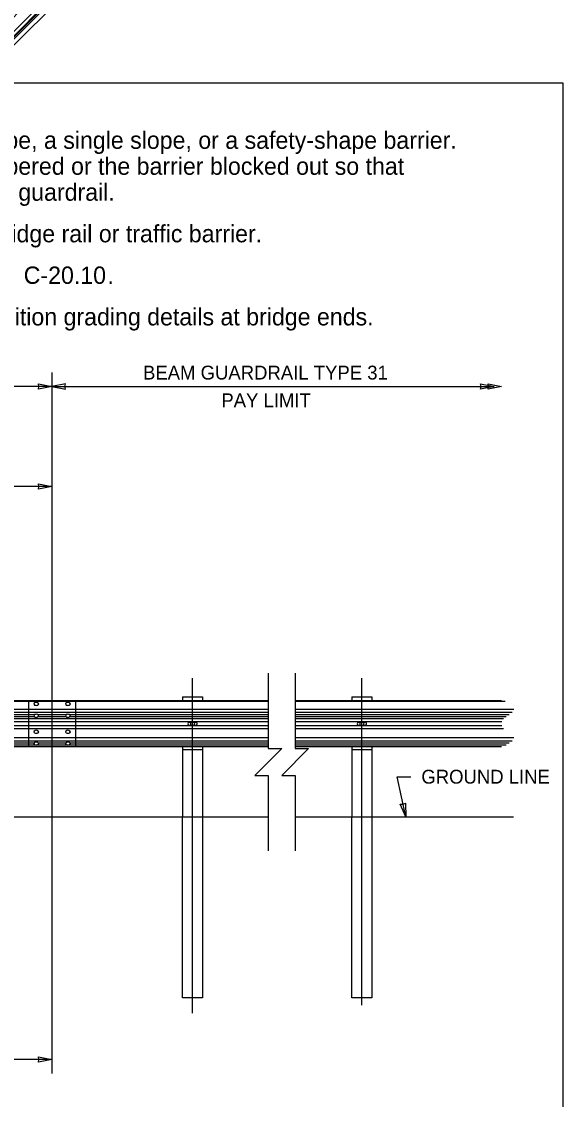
# Model space of a CAD drawing. Extents: x 34446 to 262144, y 33903 to 262144.
# Drawn here: x 102525 to 103145, y 100902 to 102147 of the extents above; entities that cross this region are included whole.
import ezdxf

# ---------------------------------------------------------------- set-up
doc = ezdxf.new("R2010")
doc.units = 0
for name, color, linetype in [('Level 1', 7, 'Continuous'), ('Level 11', 7, 'Continuous'), ('Level 12', 7, 'Continuous'), ('Level 15', 7, 'Continuous'), ('Level 2', 7, 'Continuous'), ('Level 20', 7, 'Continuous'), ('Level 5', 7, 'Continuous'), ('Level 8', 7, 'Continuous'), ('Level 9', 7, 'Continuous')]:
    doc.layers.add(name, color=color, linetype=linetype)

msp = doc.modelspace()

# ---------------------------------------------------------------- linework, layer by layer
at = {"layer": 'Level 1'}
for p, q in [((102710.8896889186, 101019.11407565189), (102710.8896889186, 101227.93343138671)), ((102733.9195840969, 101228.01685343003), (102733.9195840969, 101019.11407565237)), ((102906.69542888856, 101019.03065360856), (102906.69542888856, 101227.85000934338)), ((102929.72532406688, 101227.93343138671), (102929.72532406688, 101019.03065360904)), ((102733.9195840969, 101019.11407565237), (102710.8896889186, 101019.11407565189)), ((102929.72532406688, 101019.03065360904), (102906.69542888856, 101019.03065360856))]:
    msp.add_line(p, q, dxfattribs=at)
msp.add_lwpolyline([(99862, 99999.5), (103151, 99999.5), (103151, 102075.5), (99862, 102075.5)], close=True, dxfattribs=at)
at = {"layer": 'Level 11'}
for p, q in [((99885.83988098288, 101227.93343138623), (102809.9793919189, 101227.93343138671)), ((102840.9511302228, 101227.93343138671), (103093.23909765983, 101227.93343138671))]:
    msp.add_line(p, q, dxfattribs=at)
at = {"layer": 'Level 12'}
for p, q in [((102809.97939189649, 101362.26849800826), (101882.86191114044, 101362.26849800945)), ((102532.8619111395, 101362.26849805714), (102532.8619111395, 101308.91433139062)), ((102587.02857780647, 101362.26849805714), (102587.02857780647, 101308.91433139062)), ((103079.7091010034, 101362.26849800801), (102840.95113020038, 101362.26849800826)), ((102809.97939191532, 101308.91433138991), (101882.86191114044, 101308.91433138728)), ((103079.7091010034, 101308.91433139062), (102840.95113021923, 101308.91433138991))]:
    msp.add_line(p, q, dxfattribs=at)
for points in [[(102721.0121291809, 101337.21644837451), (102718.65357780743, 101337.21644837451)], [(102726.23691114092, 101337.21644837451), (102723.87835976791, 101337.21644837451)], [(102916.73665321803, 101337.21644837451), (102914.37810184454, 101337.21644837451)], [(102921.96143517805, 101337.21644837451), (102919.60288380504, 101337.21644837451)], [(102718.65357780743, 101333.96644837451), (102721.0121291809, 101333.96644837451)], [(102723.87835976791, 101333.96644837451), (102726.23691114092, 101333.96644837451)], [(102914.37810184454, 101333.96644837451), (102916.73665321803, 101333.96644837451)], [(102919.60288380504, 101333.96644837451), (102921.96143517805, 101333.96644837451)]]:
    msp.add_lwpolyline(points, dxfattribs=at)
for centre in [(102722.44524447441, 101335.59144837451), (102918.16976851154, 101335.59144837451)]:
    msp.add_circle(centre, 2.1666666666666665, dxfattribs=at)
for centre, start, end in [((102718.65357780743, 101335.59144837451), 90, 270), ((102726.23691114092, 101335.59144837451), 269.9999999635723, 90), ((102914.37810184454, 101335.59144837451), 90, 270), ((102921.96143517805, 101335.59144837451), 269.9999999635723, 90)]:
    msp.add_arc(centre, 1.625, start, end, dxfattribs=at)
at = {"layer": 'Level 15'}
for p, q in [((102559.94524447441, 101741.28379139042), (102559.94524447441, 100931.71120916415)), ((102559.94524447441, 101725.28379139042), (99958.9827143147, 101725.28379139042)), ((102559.94524447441, 101725.28379139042), (103070.90514361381, 101725.28379139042)), ((102559.94524447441, 101609.7282358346), (102397.44524447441, 101609.7282358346)), ((102722.44524447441, 101001.35266726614), (102722.44524447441, 101388.2667647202)), ((102918.10946834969, 101010.59243242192), (102918.10946834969, 101388.2667647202)), ((102968.84541737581, 101227.93343138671), (102958.97828765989, 101274.43452072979)), ((102958.97828765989, 101274.43452072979), (102974.90328290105, 101274.43452072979)), ((102559.94524447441, 100947.71120916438), (101909.94524447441, 100947.71120916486))]:
    msp.add_line(p, q, dxfattribs=at)
for points in [[(102559.94524447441, 101725.28379139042), (102544.21709884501, 101722.1991744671), (102544.94524447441, 101725.28379139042), (102544.21709884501, 101728.36840831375)], [(102559.94524447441, 101725.28379139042), (102575.67339010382, 101722.1991744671), (102574.94524447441, 101725.28379139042), (102575.67339010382, 101728.36840831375)], [(103070.90514361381, 101725.28379139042), (103055.17699798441, 101722.1991744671), (103055.90514361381, 101725.28379139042), (103055.17699798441, 101728.36840831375)], [(103079.7091010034, 101725.28379139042), (103063.980955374, 101722.1991744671), (103064.7091010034, 101725.28379139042), (103063.980955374, 101728.36840831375)], [(102559.94524447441, 101609.7282358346), (102544.21709884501, 101606.64361891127), (102544.94524447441, 101609.7282358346), (102544.21709884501, 101612.81285275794)], [(102968.84541737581, 101227.93343138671), (102962.56329351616, 101242.67874746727), (102965.73186917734, 101242.60673427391), (102968.59816263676, 101243.95929459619)], [(102559.94524447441, 100947.71120916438), (102544.21709884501, 100944.62659224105), (102544.94524447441, 100947.71120916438), (102544.21709884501, 100950.79582608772)]]:
    msp.add_lwpolyline(points, close=True, dxfattribs=at)
for points in [[(102809.97939188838, 101394.07740407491), (102809.9793919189, 101306.96911570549), (102825.4652610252, 101306.96911570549), (102794.49352278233, 101275.99737743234), (102809.9793919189, 101275.99737743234), (102809.9793919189, 101188.88936348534)], [(102840.95113019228, 101394.07740407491), (102840.9511302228, 101306.96911570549), (102856.43699932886, 101306.96911570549), (102825.46526105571, 101275.99737743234), (102840.9511302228, 101275.99737743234), (102840.9511302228, 101188.88936348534)]]:
    msp.add_lwpolyline(points, dxfattribs=at)
at = {"layer": 'Level 2'}
for p, q in [((102710.8896889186, 101366.60009805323), (102734.00080002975, 101366.60009805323)), ((102710.8896889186, 101366.60009805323), (102710.8896889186, 101362.26849805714)), ((102734.00080002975, 101366.60009805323), (102734.00080002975, 101362.26849805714)), ((102906.61421295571, 101366.60009805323), (102929.72532406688, 101366.60009805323)), ((102906.61421295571, 101366.60009805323), (102906.61421295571, 101362.26849805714)), ((102929.72532406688, 101366.60009805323), (102929.72532406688, 101362.26849805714)), ((102710.8896889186, 101308.91433139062), (102710.8896889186, 101305.93343138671)), ((102710.8896889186, 101305.93343138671), (102734.00080002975, 101305.93343138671)), ((102710.8896889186, 101305.93343138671), (102710.8896889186, 101227.93343138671)), ((102734.00080002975, 101308.91433139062), (102734.00080002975, 101305.93343138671)), ((102734.00080002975, 101305.93343138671), (102734.00080002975, 101227.93343138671)), ((102906.61421295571, 101308.91433139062), (102906.61421295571, 101305.93343138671)), ((102906.61421295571, 101305.93343138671), (102929.72532406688, 101305.93343138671)), ((102906.61421295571, 101305.93343138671), (102906.61421295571, 101227.93343138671)), ((102929.72532406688, 101308.91433139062), (102929.72532406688, 101305.93343138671)), ((102929.72532406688, 101305.93343138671), (102929.72532406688, 101227.93343138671))]:
    msp.add_line(p, q, dxfattribs=at)
at = {"layer": 'Level 5'}
msp.add_spline([(100965.33493063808, 100576.21973024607), (100979.73117748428, 100581.07419127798), (100976.64599230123, 100587.06308016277), (100980.63858489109, 100590.14826534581), (100978.82377007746, 100594.86678386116), (100978.82377007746, 100594.86678386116), (100972.34760629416, 100605.2602740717)], degree=3, dxfattribs=at)
at = {"layer": 'Level 8'}
for centre, start, end in [((102541.76641671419, 101356.56389125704), 50.43711929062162, 129.5628807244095), ((102578.39250793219, 101356.56389125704), 50.43711929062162, 129.56288072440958), ((102541.76627779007, 101346.78748786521), 230.4371192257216, 309.5628807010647), ((102578.39236900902, 101346.78748786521), 230.4371192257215, 309.56288070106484), ((102541.76627779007, 101324.39336530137), 50.43711929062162, 129.5628807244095), ((102578.39236900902, 101324.39336530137), 50.43711929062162, 129.56288072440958), ((102541.76627779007, 101314.6169619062), 230.4371192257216, 309.5628807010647), ((102578.39236900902, 101314.6169619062), 230.4371192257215, 309.56288070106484)]:
    msp.add_arc(centre, 3.6438845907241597, start, end, dxfattribs=at)
for centre, major_axis, ratio, start_param, end_param in [((102541.76641671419, 101358.44176386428), (2.828893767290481, 9.525007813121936e-11), 0.5757772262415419, 2.5329409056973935, 6.891810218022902), ((102541.76641671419, 101358.44176386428), (2.828893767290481, 9.525007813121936e-11), 0.5757772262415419, 0.6086249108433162, 0.6086785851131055), ((102578.39250793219, 101358.44176386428), (2.828893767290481, 9.525007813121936e-11), 0.5757772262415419, 2.532940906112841, 6.891810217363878), ((102578.39250793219, 101358.44176386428), (2.828893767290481, 9.525007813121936e-11), 0.5757772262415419, 0.6086249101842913, 0.608678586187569), ((102541.76627778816, 101344.90961525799), (2.828893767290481, -2.3947631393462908e-09), 0.5757772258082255, 5.674500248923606, 10.033404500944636), ((102541.76627778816, 101344.90961525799), (2.828893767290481, -2.3947631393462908e-09), 0.5757772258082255, 3.750219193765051, 3.7502696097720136), ((102578.39236900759, 101344.90961525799), (2.828893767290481, -2.3947631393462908e-09), 0.5757772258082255, 5.674500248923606, 10.033404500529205), ((102578.39236900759, 101344.90961525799), (2.828893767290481, -2.3947631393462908e-09), 0.5757772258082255, 3.750219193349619, 3.7502696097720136), ((102541.76627779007, 101326.2712379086), (2.828893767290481, 9.525007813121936e-11), 0.5757772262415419, 2.5329409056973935, 6.891810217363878), ((102541.76627779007, 101326.2712379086), (2.828893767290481, 9.525007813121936e-11), 0.5757772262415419, 0.6086249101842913, 0.608678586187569), ((102578.39236900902, 101326.2712379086), (2.828893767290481, 9.525007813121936e-11), 0.5757772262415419, 2.532940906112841, 6.8918102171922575), ((102578.39236900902, 101326.2712379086), (2.828893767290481, 9.525007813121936e-11), 0.5757772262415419, 0.6086249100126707, 0.608678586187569), ((102541.76627778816, 101312.73908929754), (2.828893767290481, -2.3947631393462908e-09), 0.5757772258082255, 5.674500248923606, 10.0334045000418), ((102541.76627778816, 101312.73908929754), (2.828893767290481, -2.3947631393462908e-09), 0.5757772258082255, 3.750219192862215, 3.750269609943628), ((102578.39236900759, 101312.73908929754), (2.828893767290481, -2.3947631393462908e-09), 0.5757772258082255, 5.674500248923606, 10.0334045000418), ((102578.39236900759, 101312.73908929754), (2.828893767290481, -2.3947631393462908e-09), 0.5757772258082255, 3.750219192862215, 3.750269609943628)]:
    msp.add_ellipse(centre, major_axis=major_axis, ratio=ratio, start_param=start_param, end_param=end_param, dxfattribs=at)
at = {"layer": 'Level 9'}
for p, q in [((102809.97939189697, 101361.3053243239), (101882.86191114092, 101361.3053243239)), ((102809.97939189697, 101361.3053243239), (101882.86191114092, 101361.3053243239)), ((103083.6714120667, 101361.3053243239), (102840.95113020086, 101361.3053243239)), ((103083.6714120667, 101361.3053243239), (102840.95113020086, 101361.3053243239)), ((102809.97939190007, 101352.00609539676), (101882.86191114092, 101352.00609539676)), ((102809.97939190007, 101352.00609539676), (101882.86191114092, 101352.00609539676)), ((102809.97939190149, 101348.4860271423), (101882.86191114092, 101348.4860271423)), ((102809.97939190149, 101348.4860271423), (101882.86191114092, 101348.4860271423)), ((103093.70317628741, 101352.00609539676), (102840.95113020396, 101352.00609539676)), ((103093.70317628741, 101352.00609539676), (102840.95113020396, 101352.00609539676)), ((103091.87612891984, 101348.4860271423), (102840.9511302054, 101348.4860271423)), ((103091.87612891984, 101348.4860271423), (102840.9511302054, 101348.4860271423)), ((102809.97939190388, 101341.31336069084), (101882.86191114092, 101341.31336069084)), ((102809.97939190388, 101341.31336069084), (101882.86191114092, 101341.31336069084)), ((102809.97939190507, 101338.01407059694), (101882.86191114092, 101338.01407059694)), ((102809.97939190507, 101338.01407059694), (101882.86191114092, 101338.01407059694)), ((102539.82638730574, 101346.09513831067), (101930.3322594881, 101346.09513831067)), ((102539.82638730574, 101346.09513831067), (101930.3322594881, 101346.09513831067)), ((102539.82423351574, 101343.70424947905), (101930.33441328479, 101343.70424947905)), ((102539.82423351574, 101343.70424947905), (101930.33441328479, 101343.70424947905)), ((102576.45247852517, 101346.09513831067), (102543.70616826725, 101346.09513831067)), ((102576.45247852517, 101346.09513831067), (102543.70616826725, 101346.09513831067)), ((102576.45032473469, 101343.70424947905), (102543.7083220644, 101343.70424947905)), ((102576.45032473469, 101343.70424947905), (102543.7083220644, 101343.70424947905)), ((102809.9793919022, 101346.09513831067), (102580.33225948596, 101346.09513831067)), ((102809.9793919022, 101346.09513831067), (102580.33225948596, 101346.09513831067)), ((102809.97939190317, 101343.70424947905), (102580.33441328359, 101343.70424947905)), ((102809.97939190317, 101343.70424947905), (102580.33441328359, 101343.70424947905)), ((103088.48105452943, 101346.09513831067), (102840.95113020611, 101346.09513831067)), ((103088.48105452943, 101346.09513831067), (102840.95113020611, 101346.09513831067)), ((103085.08598009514, 101343.70424947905), (102840.95113020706, 101343.70424947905)), ((103085.08598009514, 101343.70424947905), (102840.95113020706, 101343.70424947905)), ((103081.69090566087, 101341.31336069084), (102840.95113020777, 101341.31336069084)), ((103081.69090566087, 101341.31336069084), (102840.95113020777, 101341.31336069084)), ((103079.978920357, 101338.01407059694), (102840.95113020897, 101338.01407059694)), ((103079.978920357, 101338.01407059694), (102840.95113020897, 101338.01407059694)), ((102809.97939190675, 101333.16875884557), (101882.86191114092, 101333.16875884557)), ((102809.97939190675, 101333.16875884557), (101882.86191114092, 101333.16875884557)), ((102809.97939190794, 101329.8694687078), (101882.86191114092, 101329.8694687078)), ((102809.97939190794, 101329.8694687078), (101882.86191114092, 101329.8694687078)), ((103079.97892040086, 101333.16875884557), (102840.95113021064, 101333.16875884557)), ((103079.97892040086, 101333.16875884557), (102840.95113021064, 101333.16875884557)), ((103081.69090566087, 101329.8694687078), (102840.95113021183, 101329.8694687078)), ((103081.69090566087, 101329.8694687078), (102840.95113021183, 101329.8694687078)), ((102809.97939191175, 101319.17673404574), (101882.86191114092, 101319.17673404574)), ((102809.97939191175, 101319.17673404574), (101882.86191114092, 101319.17673404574)), ((102809.97939191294, 101315.65666579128), (101882.86191114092, 101315.65666579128)), ((102809.97939191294, 101315.65666579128), (101882.86191114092, 101315.65666579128)), ((102539.08936037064, 101313.26577695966), (101931.06928642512, 101313.26577695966)), ((102539.08936037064, 101313.26577695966), (101931.06928642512, 101313.26577695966)), ((102575.71545159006, 101313.26577695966), (102544.44319520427, 101313.26577695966)), ((102575.71545159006, 101313.26577695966), (102544.44319520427, 101313.26577695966)), ((102809.97939191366, 101313.26577695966), (102581.06928642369, 101313.26577695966)), ((102809.97939191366, 101313.26577695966), (102581.06928642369, 101313.26577695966)), ((103093.70317628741, 101319.17673404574), (102840.95113021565, 101319.17673404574)), ((103093.70317628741, 101319.17673404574), (102840.95113021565, 101319.17673404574)), ((103091.87612891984, 101315.65666579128), (102840.95113021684, 101315.65666579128)), ((103091.87612891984, 101315.65666579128), (102840.95113021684, 101315.65666579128)), ((103088.48105452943, 101313.26577695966), (102840.95113021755, 101313.26577695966)), ((103088.48105452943, 101313.26577695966), (102840.95113021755, 101313.26577695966)), ((102809.9793919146, 101310.87488812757), (101882.86191114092, 101310.87488812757)), ((102809.9793919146, 101310.87488812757), (101882.86191114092, 101310.87488812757)), ((103085.08598009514, 101310.87488812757), (102840.95113021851, 101310.87488812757)), ((103085.08598009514, 101310.87488812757), (102840.95113021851, 101310.87488812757))]:
    msp.add_line(p, q, dxfattribs=at)

# ---------------------------------------------------------------- texts
at = {"layer": 'Level 20'}
for s, height, p in [('This guardrail transition is for connection to a vertical concrete shape, a single slope, or a safety-shape barrier.  ', 19.999997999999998, (101721.17633654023, 101999.80496616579)), ('The toe of the single slope and the safety-shape barrier shall be tapered or the barrier blocked out so that ', 19.999997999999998, (101721.17633654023, 101969.80496916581)), ('the toe of the barrier does not project past the face of the approach guardrail.', 19.999997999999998, (101721.17633654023, 101939.80497216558)), (' for details regarding connection to bridge rail or traffic barrier.', 19.999997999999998, (102071.47659447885, 101891.80497616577)), (' C-20.10', 19.999997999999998, (102519.8481316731, 101843.80498016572)), ('.', 19.999997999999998, (102624.044898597, 101843.80498016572)), (' for beam guardrail transition grading details at bridge ends. ', 19.999997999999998, (102225.4951337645, 101795.80498416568)), ('BEAM GUARDRAIL TYPE 31', 16, (102665.1549250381, 101733.28379139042)), ('PAY LIMIT', 16, (102755.7144953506, 101701.28379139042)), ('GROUND LINE', 16.000002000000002, (102986.90328290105, 101266.43451972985))]:
    msp.add_text(s, height=height, dxfattribs=at).set_placement(p)

doc.saveas('drawing.dxf')
